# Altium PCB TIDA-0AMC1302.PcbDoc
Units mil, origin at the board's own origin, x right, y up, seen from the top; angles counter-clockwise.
Board outline 1945 x 1500 mil, 2 copper layers (Top Layer, Bottom Layer), stack 62 mil thick; 63 components, 28 nets, 133 pads, 62 vias.
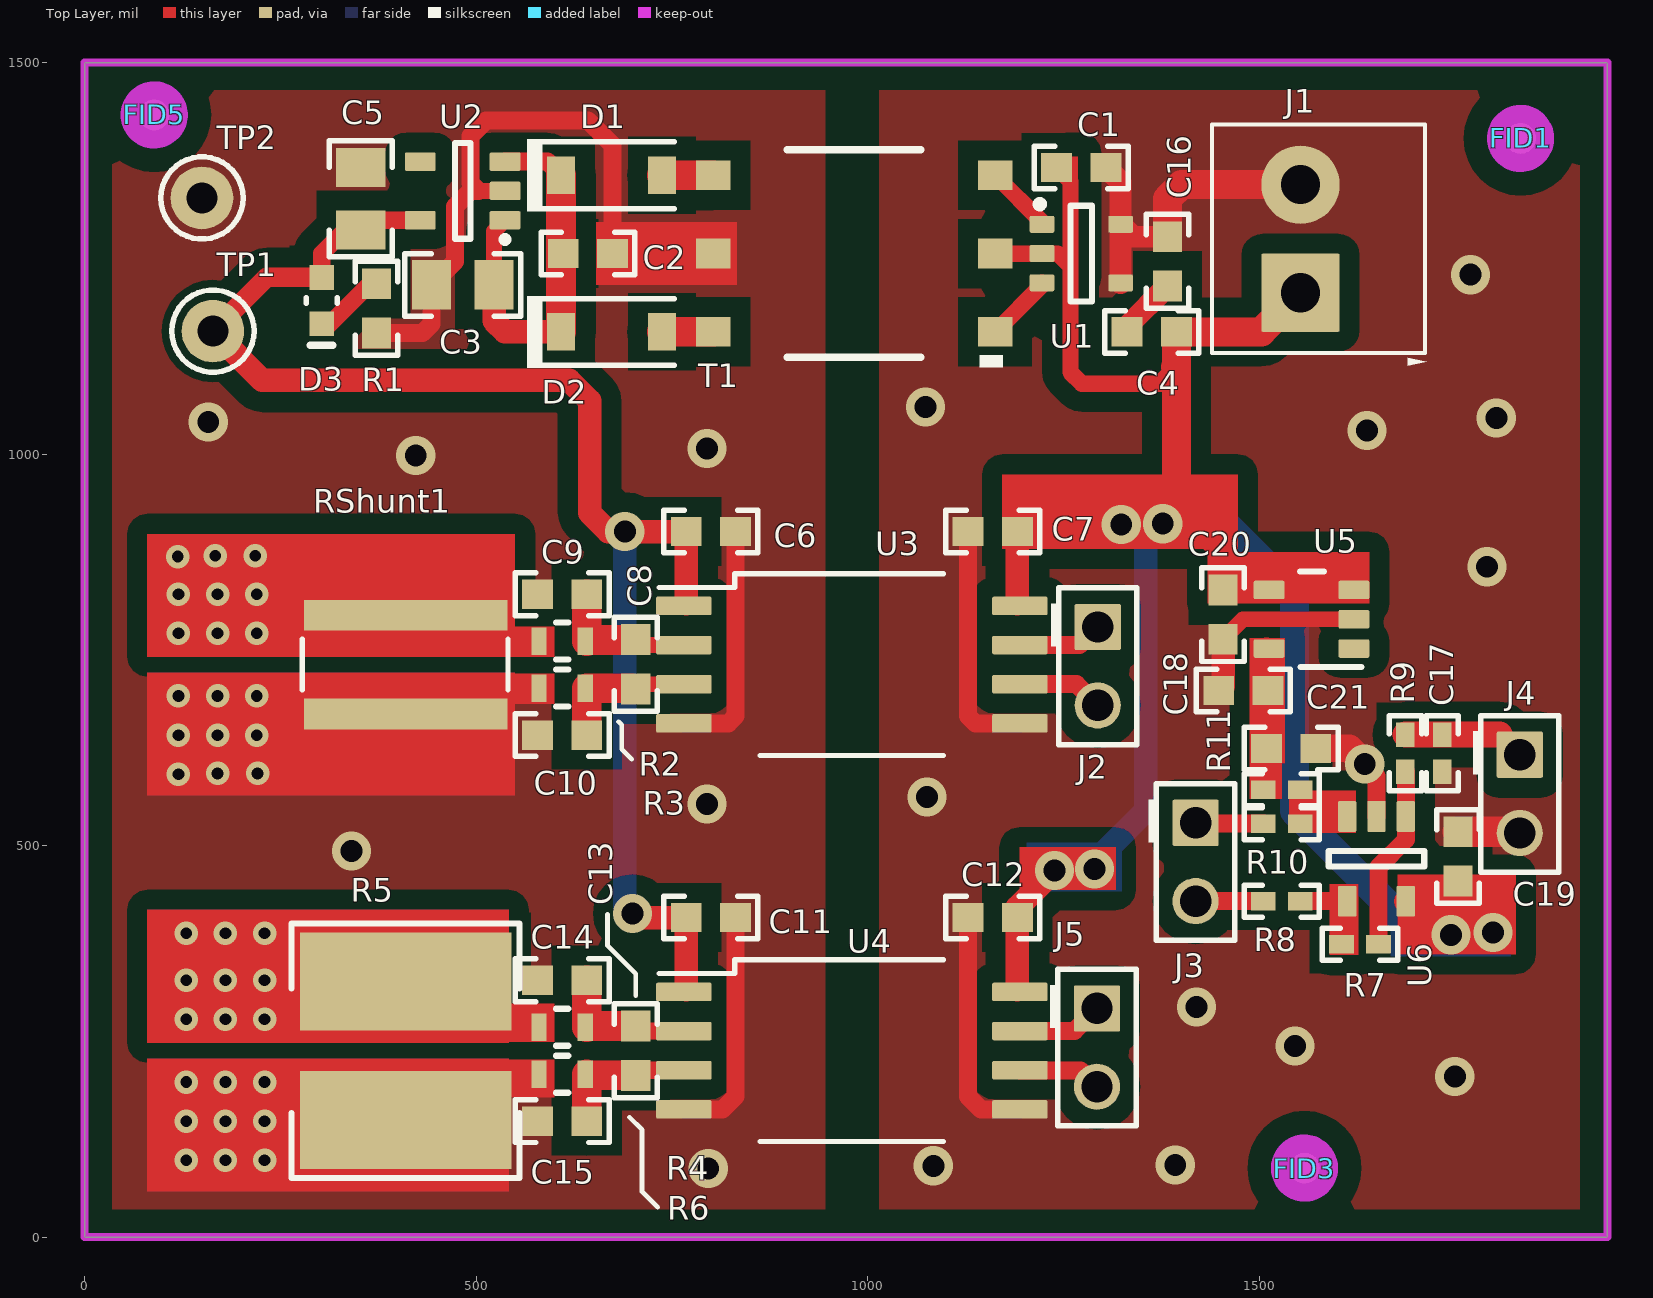
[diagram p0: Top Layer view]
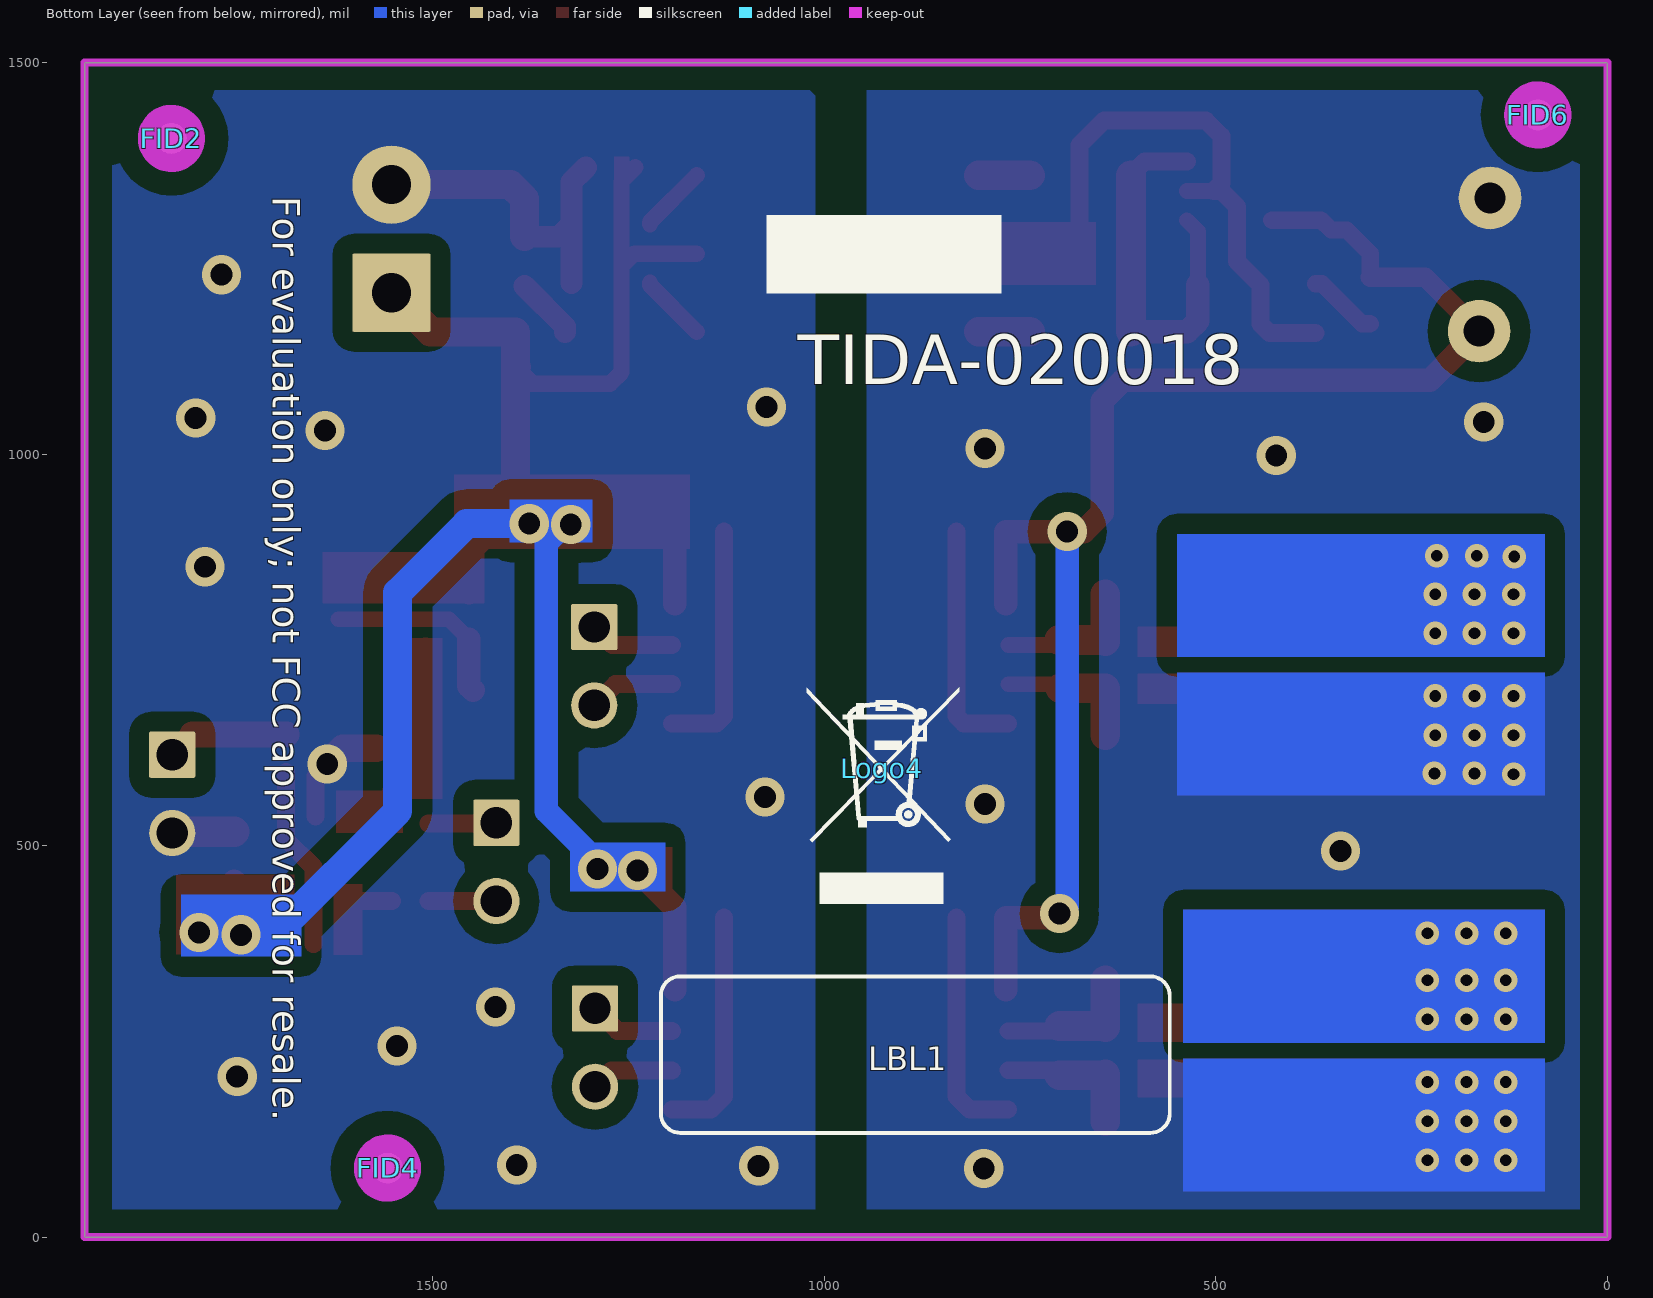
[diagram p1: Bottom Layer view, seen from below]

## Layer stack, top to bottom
Top Solder: solder mask 0.4, Solder Resist, Dk 3.5
Top Layer: signal copper 1.4
Dielectric1: core 59.2, FR-4, Dk 4.8
Bottom Layer: signal copper 1.4
Bottom Solder: solder mask 0.4, Solder Resist, Dk 3.5

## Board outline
0,0 1945,0 1945,1500 0,1500

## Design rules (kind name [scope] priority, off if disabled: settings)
AcuteAngle [All] p1: minimum=4.50000000000000E+0001 checktracksonly=FALSE
AssemblyTestPointUsage [All] p1: valid=2
Clearance samenet [IsPad vs IsVia] p1: gap=6 ignorepadtopadclearanceinfootprint=FALSE except(0: Arc-SMDPad Arc-Hole Track-Hole SMDPad-Hole THPad-Hole Via-Hole Fill-Hole Poly-Hole Region-Hole Text-Hole)
Clearance Clearance_Keepouts [IsKeepOut] p2: gap=30 ignorepadtopadclearanceinfootprint=FALSE except(0: Arc-SMDPad Arc-Hole Track-Hole SMDPad-Hole THPad-Hole Via-Hole Fill-Hole Poly-Hole Region-Hole Text-Hole)
Clearance Clearance_Poly [InPolygon] p3: gap=25 ignorepadtopadclearanceinfootprint=FALSE except(0: Arc-SMDPad Arc-Hole Track-Hole SMDPad-Hole THPad-Hole Via-Hole Fill-Hole Poly-Hole Region-Hole Text-Hole)
Clearance Clearance_FiducialMark [IsKeepOut and InComponentClass('FiducialMark') vs IsPad and InComponentClass('FiducialMark')] p4: gap=0 ignorepadtopadclearanceinfootprint=FALSE
Clearance [All] p5: gap=7.87 ignorepadtopadclearanceinfootprint=FALSE except(0: Arc-SMDPad Arc-Hole Track-Hole SMDPad-Hole THPad-Hole Via-Hole Fill-Hole Poly-Hole Region-Hole Text-Hole)
ComponentClearance ComponentClearance_MountingHoles_FiducialMarks [InComponentClass('Mounting Holes') vs InComponentClass('FiducialMark')] p1: gap=50 collisioncheckmode=3 verticalgap=10 showdistances=FALSE
ComponentClearance ComponentClearance_Shunt [InComponentClass('Header') vs InComponentClass('Shunt')] p2: gap=0 collisioncheckmode=3 verticalgap=0 showdistances=FALSE
ComponentClearance ComponentClearance_Logo [InComponentClass('Logo')] p3: gap=10 collisioncheckmode=3 verticalgap=10 showdistances=FALSE
ComponentClearance ComponentClearance_ScrewToNut [(HasFootprint('NY PMS 440 0025 PH')) vs (HasFootprint('Keystone_1902C'))] p4: gap=5 collisioncheckmode=3 verticalgap=10 showdistances=FALSE
ComponentClearance ComponentClearance_MountingHoles [InComponentClass('Mounting Holes')] p5: gap=250 collisioncheckmode=3 verticalgap=100000 showdistances=FALSE
ComponentClearance ComponentClearance_SmallPassives [HasFootprint('0201*') or HasFootprint('0402*') or HasFootprint('0508') or HasFootprint('0603*') or HasFootprint('0612') or HasFootprint('0805*') or HasFootprint('0815*') or HasFootprint('0830*') or HasFootprint('1206*') or HasFootprint('1210*') or HasFootprint('1808*') or HasFootprint('1812*') or HasFootprint('1825*') or HasFootprint('2010*') or HasFootprint('2220*') or HasFootprint('2225*') or HasFootprint('2512*') or HasFootprint('2728*') or HasFootprint('3518*') vs HasFootprint('0201*') or HasFootprint('0402*') or HasFootprint('0508') or HasFootprint('0603*') or HasFootprint('0612') or HasFootprint('0805*') or HasFootprint('0815*') or HasFootprint('0830*') or HasFootprint('1206*') or HasFootprint('1210*') or HasFootprint('1808*') or HasFootprint('1812*') or HasFootprint('1825*') or HasFootprint('2010*') or HasFootprint('2220*') or HasFootprint('2225*') or HasFootprint('2512*') or HasFootprint('2728*') or HasFootprint('3518*')] p6: gap=14.96 collisioncheckmode=3 verticalgap=10 showdistances=FALSE
ComponentClearance ComponentClearance_THtoSMT [IsThruComponent vs IsSMTComponent] p7: gap=10 collisioncheckmode=3 verticalgap=10 showdistances=FALSE
ComponentClearance ComponentClearance_THtoTH [IsThruComponent vs IsThruComponent] p8: gap=30 collisioncheckmode=3 verticalgap=30 showdistances=FALSE
ComponentClearance [All] p9: gap=10 collisioncheckmode=3 verticalgap=10 showdistances=FALSE
DiffPairsRouting [All] p1: maxlimit=100 minlimit=10 mostfreqgap=10 toplayer_minwidth=15 toplayer_maxwidth=15 toplayer_prefwidth=15 bottomlayer_minwidth=15 bottomlayer_maxwidth=15 bottomlayer_prefwidth=15 maxuncoupledlength=1000
FabricationTestPointUsage TestPointUsage [All] p1: valid=2 allowmultiple=FALSE
FabricationTestpoint Testpoint [All] p1: side=3 testpointundercomponent=TRUE minsize=40 maxsize=100 preferedsize=60 minholesize=0 maxholesize=40 preferedholesize=32 testpointgrid=1 allowsidetop=TRUE allowsidebottom=TRUE usegrid=TRUE gridtolerance=0.01
FanoutControl Fanout_LCC [IsLCC] p1: bgadir=Out bgaviamode=Centered fanoutstyle=Auto fanoutdirection=Alternating viagrid=1 // Fanout_LCC (Default Rule)
FanoutControl Fanout_BGA [IsBGA] p2: bgadir=Out bgaviamode=Centered fanoutstyle=Auto fanoutdirection=Alternating viagrid=1 // Fanout_BGA (Default Rule)
FanoutControl Fanout_Default [All] p4: bgadir=Out bgaviamode=Centered fanoutstyle=Auto fanoutdirection=Alternating viagrid=1 // Fanout_Default (Default Rule)
FanoutControl Fanout_Small [(CompPinCount < 5)] p5: bgadir=Out bgaviamode=Centered fanoutstyle=Auto fanoutdirection=OutThenIn viagrid=1 // Fanout_Small (Default Rule)
HoleSize [All] p1: absolutevalues=TRUE maxlimit=251 minlimit=7.87 maxpercent=80.000 minpercent=20.000
MinimumAnnularRing MinimumAnnularRing_ThermalPadVias [IsVia and InAnyComponent] p1: minimumring=5.91
MinimumAnnularRing [All] p2: minimumring=6
MinimumSolderMaskSliver MinimumSolderMaskSliver_Logo [InComponentClass('Logo') vs InComponentClass('Logo')] p1: minsoldermaskwidth=0.7
MinimumSolderMaskSliver [All] p2: minsoldermaskwidth=3.94
PlaneConnect [All] p1: planeconnectstyle=Relief reliefexpansion=10 reliefentries=4 reliefconductorwidth=10 reliefairgap=10
PolygonConnect [All] p1: connectstyle=Direct reliefconductorwidth=10 reliefentries=4 polygonreliefangle="90 Angle" airgapwidth=10
RoutingVias ThermalPadVias [IsVia and InAnyComponent] p1: holewidth=7.87 width=19.68 viastyle="Through Hole" minholewidth=7.87 minwidth=19.68 maxholewidth=12.99 maxwidth=23.62
RoutingVias [All] p2: holewidth=16 width=34 viastyle="Through Hole" minholewidth=7.87 minwidth=26 maxholewidth=40 maxwidth=65
SilkToBoardRegionClearance [Not ((IsComment or IsDesignator) And (Hide <> 'False')) and not InRegion(1000,500,4000,800)] p1:
SilkToSilkClearance SilkToSilkClearance_Pb-FreeLogo [(HasFootprint('Pb-Free_Overlay_Medium') OR HasFootprint('Pb-Free_Overlay_Small')) vs (HasFootprint('Pb-Free_Overlay_Medium') OR HasFootprint('Pb-Free_Overlay_Small'))] p1: silktosilkclearance=0
SilkToSilkClearance [All] p2: silktosilkclearance=4
SilkToSolderMaskClearance SilkToComponentPadClearance [(IsPad or IsFill or IsRegion) and InAnycomponent] p1: minsilkscreentomaskgap=5 clearancetoexposedcopper=TRUE
SilkToSolderMaskClearance "Silk to Solder Mask Opening" [All] p2: minsilkscreentomaskgap=4 clearancetoexposedcopper=FALSE
SolderMaskExpansion [All] p1: expansion=1.97
Width [All] p1: maxlimit=100 minlimit=6 preferedwidth=10 checkconnectedcopper=TRUE
15 further rules are at their usual default settings.

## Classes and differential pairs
component class Header: J2 J3 J4 J5
component class EVM_Hardware: FID1 FID2 FID3 FID4 FID5 FID6 LBL1 Logo3 Logo4 ZZ1 ZZ2 ZZ3 ZZ4
component class FiducialMark: FID1 FID2 FID3 FID4 FID5 FID6
component class AssemblyNote: ZZ1 ZZ2 ZZ3 ZZ4
component class Label: LBL1
component class BlankSheet: C1 C2 C3 C4 C5 C6 C7 C8 C9 C10 C11 C12 C13 C14 C15 C16 C17 C18 C19 C20 C21 D1 D2 D3 J1 J2 J3 J4 J5 R1 R2 R3 R4 R5 R6 R7 R8 R9 R10 R11 RShunt1 T1 TP1 TP2 U1 U2 U3 U4 U5 U6

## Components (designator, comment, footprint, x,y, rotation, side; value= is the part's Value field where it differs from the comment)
C1 "UMK107AB7105KA-T" 0603 1273,1366 r180 top value=1uF
C2 "C1608X7R1E104K080AA" 0603 643,1256 r0 top value=0.1uF
C3 "JMK212BJ226MG-T" 0805_HV 483,1216 r180 top value=22uF
C4 "C1608X7R1E104K080AA" 0603 1363,1156 r180 top value=0.1uF
C5 "JMK212BJ226MG-T" 0805_HV 352.84,1326 r90 top value=22uF
C6 "C1608X7R1E104K080AA" 0603 800,901 r180 top value=0.1uF
C7 "C1608X7R1E104K080AA" 0603 1160,901 r180 top value=0.1uF
C8 "C1608X7R1E104K080AA" 0603 704,731.5 r270 top value=0.1uF
C9 "CL10B103KB8NCNC" 0603 610,821 r180 top value=0.01uF
C10 "CL10B103KB8NCNC" 0603 610,641 r180 top value=0.01uF
C11 "C1608X7R1E104K080AA" 0603 800,408 r180 top value=0.1uF
C12 "C1608X7R1E104K080AA" 0603 1160,408 r180 top value=0.1uF
C13 "C1608X7R1E104K080AA" 0603 704,238 r270 top value=0.1uF
C14 "CL10B103KB8NCNC" 0603 610,328 r180 top value=0.01uF
C15 "CL10B103KB8NCNC" 0603 610,148 r180 top value=0.01uF
C16 "C1608X7R1E104K080AA" 0603 1383,1246 r90 top value=0.1uF
C17 "C1005X7R1C224K050BC" 0402 1734,618 r270 top value=0.22uF
C18 "C1608X7R1E104K080AA" 0603 1480,698 r180 top value=0.1uF
C19 "C1608X7R1E104K080AA" 0603 1754,486 r270 top value=0.1uF
C20 "C1608X7R1E104K080AA" 0603 1454,795 r90 top value=0.1uF
C21 "C1608X7R1E104K080AA" 0603 1541,624 r0 top value=0.1uF
D1 "MBR0520LT1G" SOD-123 673,1356 r0 top value=20V
D2 "MBR0520LT1G" SOD-123 673,1156 r0 top value=20V
D3 "LG L29K-G2J1-24-Z" "LG L29K_GREEN" 303,1196 r270 top value=Green
FID1 "Fiducial" Fiducial10-20 1834,1403 r0 top
FID2 "Fiducial" Fiducial10-20 1834,1403 r180 bottom
FID3 "Fiducial" Fiducial10-20 1558,88 r0 top
FID4 "Fiducial" Fiducial10-20 1558,88 r180 bottom
FID5 "Fiducial" Fiducial10-20 89,1433 r0 top
FID6 "Fiducial" Fiducial10-20 89,1433 r180 bottom
J1 "ED555/2DS" TERM_BLK_ED555-2DS 1553,1206 r90 top
J2 "PEC02SAAN" CONN_PEC02SAAN 1294,729 r270 top
J3 "PEC02SAAN" CONN_PEC02SAAN 1419,479 r270 top
J4 "PEC02SAAN" CONN_PEC02SAAN 1833,566 r270 top
J5 "PEC02SAAN" CONN_PEC02SAAN 1293,242 r270 top
LBL1 "THT-14-423-10" Label_650x200 884,233 r180 bottom
Logo3 "FCC disclaimer" FCC_disclaimer 2657,717 r180 bottom
Logo4 "WEEE logo" WEEE_Minimum 927,598 r180 bottom
R1 "CRCW06034K70JNEA" 0603 373,1186 r90 top value=4.7k
R2 "TNPW060349R9BEEA" TNPW0603 610,761 r0 top value=49.9
R3 "TNPW060349R9BEEA" TNPW0603 610,701 r0 top value=49.9
R4 "TNPW060349R9BEEA" TNPW0603 610,268 r0 top value=49.9
R5 "CSS2725FTL500" CSS2725_0005 410,238 r90 top value=0.0005
R6 "TNPW060349R9BEEA" TNPW0603 610,208 r0 top value=49.9
R7 "ERA-2AEB1212X" 0402 1629,374 r0 top value=12.1k
R8 "RT0402BRD0710KL" 0402 1529,429 r0 top value=10.0k
R9 "FC0402E50R0BST1" 0402 1687,618 r90 top value=50
R10 "RT0402BRD0710KL" 0402 1529,528 r0 top value=10.0k
R11 "ERA-2AEB1212X" 0402 1529,571 r0 top value=12.1k
RShunt1 "PML100HZPJV1L5" 2512_WIDE 410,731 r90 top value=0.0015
T1 "760390014" Wurth_760390013 983,1256 r180 top value=475uH
TP1 "5001" Keystone5001 164,1157 r90 top
TP2 "5001" Keystone5001 150,1327 r90 top
U1 "SN6501QDBVRQ1" DBV0005A_L 1273,1256 r0 top
U2 "TPS76350QDBVRQ1" DBV0005A_N 483,1336 r180 top
U3 "AMC1302QDWVRQ1" DWV0008A 980,731 r0 top
U4 "AMC1302QDWVRQ1" DWV0008A 980,238 r0 top
U5 "LM4132AQ1MFT2.5" DBV0005A_N 1567,789 r180 top
U6 "OPA376AQDBVRQ1" DBV0005A_N 1650,483 r270 top
ZZ1 "This Assembly Note is for PCB labels only" AssemblyNoteLabel 185,3938 r0 top
ZZ2 "These assemblies are ESD sensitive, ESD precautions shall be observed." AssemblyNote 185,3829.11 r0 top
ZZ3 "These assemblies must be clean and free from flux and all contaminants. Use of no clean flux is not acceptable." AssemblyNote 185,3740.56 r0 top
ZZ4 "These assemblies must comply with workmanship standards IPC-A-610 Class 2, unless otherwise specified." AssemblyNote 185,3652 r0 top

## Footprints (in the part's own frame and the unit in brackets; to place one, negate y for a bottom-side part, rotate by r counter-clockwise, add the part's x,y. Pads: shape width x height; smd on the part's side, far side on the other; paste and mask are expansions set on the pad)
0402 [mm] "0402 from SM-752 data"
  rect 0.8x0.6 smd: 1(-0.6,0) 2(0.6,0)
  silkscreen extent -1.22,-0.52 1.22,0.52, body extent -0.55,-0.3 0.55,0.3, height 0.6
0603 [mm] "0603 from SM-752 data"
  rect 1x0.95 smd: 1(-0.8,0) 2(0.8,0)
  silkscreen extent -1.52,-0.69 1.52,0.69, body extent -0.87,-0.47 0.87,0.47, height 1
0805_HV [mil] "0805 with 30mil clearance between pads"
  rect 50x63 smd: 1(-40,0) 2(40,0)
  silkscreen extent -74,-40 74,40, body extent -43,-29 43,29, height 57
2512_WIDE [mm] "Ohmite recommended land pattern"
  rect 1x6.6 smd: 1(-1.6,0) 2(1.6,0)
  silkscreen extent -0.82,-3.32 0.82,3.35, body extent -1.65,-3.25 1.65,3.25, height 0.7
AssemblyNote [mil] "Assembly Note"
AssemblyNoteLabel [mil] "Assembly Note for PCB Labels"
CONN_PEC02SAAN [mm] "SULLINS"
  rrect7% 1.5x1.5 hole 1.016: 1(-1.27,0)
  round 1.5 hole 1.016: 2(1.27,0)
  silkscreen extent -2.54,-1.52 2.54,1.27, body extent -2.54,-1.27 2.54,1.27, height 8.38
CSS2725_0005 [mm] "STACKPOLE ELECTRONICS"
  rect 3.18x6.86 smd: 1(-2.25,0) 2(2.25,0)
  silkscreen extent -4.13,-3.7 4.13,3.7, body extent -3.53,-3.35 3.53,3.35, height 1.24
DBV0005A_L [mm] "SOT23, 5-Leads, Body 2.9x1.6mm, Pitch 0.95mm, Lead Span 2.8mm, IPC High Density"
  rrect18% 0.8x0.55 smd: 1(-1.275,0.95) 2(-1.275,0) 3(-1.275,-0.95) 4(1.275,-0.95) 5(1.275,0.95)
  silkscreen extent -0.35,-1.55 0.35,1.55, body extent -1.42,-1.46 1.42,1.46, height 1.09
DBV0005A_N [mm] "SOT23, 5-Leads, Body 2.9x1.6mm, Pitch 0.95mm, Lead Span 2.8mm, IPC Medium Density"
  rrect17% 1x0.6 smd: 1(-1.375,0.95) 2(-1.375,0) 3(-1.375,-0.95) 4(1.375,-0.95) 5(1.375,0.95)
  silkscreen extent -0.25,-1.55 0.25,1.55, body extent -1.42,-1.46 1.42,1.46, height 1.09
DWV0008A [mm] "SOIC, 8-Leads, Body 5.95x7.6mm (max), Pitch 1.27mm"
  rrect17% 1.8x0.6 smd: 1(-5.45,1.905) 2(-5.45,0.635) 3(-5.45,-0.635) 4(-5.45,-1.905) 5(5.45,-1.905) 6(5.45,-0.635) 7(5.45,0.635) 8(5.45,1.905)
  silkscreen extent -6.25,-2.95 2.98,2.95, body extent -5.77,-2.92 5.77,2.93, height 2.67
FCC_disclaimer [mil]
Fiducial10-20 [mm]
  round 1 smd mask+0.5: 1(0,0)
  Top Layer keep-out circle w1.178: c0,0 r0.5
Keystone5001 [mil] "For Keystone 500x miniature loop terminals"
  round 80 hole 40: 1(0,0)
  silkscreen extent -52,-52 52,52, body extent -49,-49 49,49, height 182
Label_650x200 [mil] "Thermal Transfer Label"
  round 1 on Mech14: 0(0,0)
  silkscreen extent -325,-100 325,100, body extent -325,-100 325,100, height 1
"LG L29K_GREEN" [mm] "OSRAM"
  rect 0.8x0.8 smd paste-0.4: 1(-0.75,0) 2(0.75,0)
  silkscreen extent -0.1,-0.5 1.45,0.5, body extent -0.9,-0.45 0.9,0.45, height 0.67
SOD-123 [mm] "On Semi recommended land pattern"
  rect 0.915x1.22 smd: 1(-1.637,0) 2(1.637,0)
  silkscreen extent -2.74,-1.17 2.03,1.17, body extent -1.93,-0.9 1.93,0.9, height 1.35
TERM_BLK_ED555-2DS [mil]
  rrect4% 100x100 hole 50: 1(0,0)
  round 100 hole 50: 2(138,0)
  silkscreen extent -93,-161 215,113, body extent -69,-150 207,106, height 323
TNPW0603 [mm] "Vishay"
  rect 0.5x0.9 smd: 1(-0.75,0) 2(0.75,0)
  silkscreen extent -0.2,-0.6 0.2,0.6, body extent -0.85,-0.47 0.85,0.47, height 0.55
WEEE_Minimum [mil] "WEEElie bin"
  silkscreen extent -95,-172 99,104
Wurth_760390013 [mil] "Wurth"
  rect 44x38 smd: 1(-180,100) 2(-180,0) 3(-180,-100) 4(180,-100) 5(180,0) 6(180,100)
  silkscreen extent -190,-132 85,145, body extent -198,-135 198,130, height 166

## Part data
C1: library part CMP-0007508-5, "CAP, CERM, 1 uF, 50 V, +/- 10%, X7R, 0603", Cap_Case=0603, Manufacturer="Taiyo Yuden", Supplier Part Number 1=587-3247-1-ND, TempCo=X7R, Tolerance_%=10%, Value1=Unknown, Value2=50V, ValueDisplayed=1uF
C2 C4 C6 C7 C8 C11 C12 C13 C16 C18 C19 C20 C21: library part CMP-0007039-5, "CAP, CERM, 0.1 uF, 25 V, +/- 10%, X7R, 0603", Cap_Case=0603, Manufacturer=TDK, Supplier Part Number 1=445-1316-1-ND, TempCo=X7R, Tolerance_%=10%, Value1=Unknown, Value2=25V, ValueDisplayed=0.1uF
C3 C5: library part CMP-0008391-2, "CAP, CERM, 22 uF, 6.3 V, +/- 20%, X5R, 0805", Cap_Case=0805, Manufacturer="Taiyo Yuden", Supplier Part Number 1=587-1305-1-ND, TempCo=X5R, Tolerance_%=20%, Value1=Unknown, Value2=6.3V, ValueDisplayed=22uF
C9 C10 C14 C15: library part CMP-0007109-5, "CAP, CERM, 0.01 uF, 50 V, +/- 10%, X7R, 0603", Cap_Case=0603, Manufacturer="Samsung Electro-Mechanics", Supplier Part Number 1=1276-1921-1-ND, TempCo=X7R, Tolerance_%=10%, Value1=Unknown, Value2=50V, ValueDisplayed=0.01uF
C17: library part CMP-0006293-2, "CAP, CERM, 0.22 uF, 16 V, +/- 10%, X7R, 0402", Cap_Case=0402, Manufacturer=TDK, Supplier Part Number 1=445-5936-1-ND, TempCo=X7R, Tolerance_%=10%, Value1=Unknown, Value2=16V, ValueDisplayed=0.22uF
D1 D2: library part CMP-0028524-1, "Diode, Schottky, 20 V, 0.5 A, SOD-123", Manufacturer="ON Semiconductor", Supplier Part Number 1=MBR0520LT1GOSCT-ND, Value1=0.5A, Value2=0.385V
D3: library part CMP-0002874-1, "LED, Green, SMD", Color=green, Manufacturer=OSRAM, Supplier Part Number 1=475-2709-1-ND, Value1=W, Value2=1.7V
FID1 FID2 FID3 FID4 FID5 FID6: library part CMP-0077181-1, "Fiducial mark.  There is nothing to buy or mount.", Manufacturer=N/A
J1: library part CMP-0074913-1, "Terminal Block, 3.5mm Pitch, 2x1, TH", Color=Grey, Current_A=6A, Manufacturer="On-Shore Technology", Supplier Part Number 1=ED1514-ND, Voltage_V=150V
J2 J3 J4 J5: library part CMP-0002337-1, "Header, 100mil, 2x1, Tin, TH", Color=Black, Current_A=3A, Manufacturer="Sullins Connector Solutions", Supplier Part Number 1=S1012E-02-ND, Voltage_V=1.8kV
LBL1: library part CMP-0003625-1, "Thermal Transfer Printable Labels, 0.650\" W x 0.200\" H - 10,000 per roll", Manufacturer=Brady, Supplier Part Number 1=97C5133
Logo3: library part CMP-0074847-1, "FCC_disclaimer"
Logo4: library part CMP-0074769-1
R1: library part CMP-0025817-4, "RES, 4.7 k, 5%, 0.1 W, AEC-Q200 Grade 0, 0603", Manufacturer=Vishay-Dale, Power_W=100mW, Supplier Part Number 1=541-4.7KGCT-ND, TempCo="200 ppm/C", Tolerance_%=5%, Value2=0.1W, Value_Code=4k70, ValueDisplayed=4.7k
R2 R3 R4 R6: library part CMP-0025693-1, "RES, 49.9, 0.1%, 0.1 W, AEC-Q200 Grade 1, 0603", Manufacturer=Vishay-Dale, Power_W=100mW, Supplier Part Number 1=541-2031-1-ND, TempCo="25 ppm/C", Tolerance_%=0.1%, Value2=0.1W, Value_Code=49R9, ValueDisplayed=49.9
R5: library part CMP-0015026-2, "RES, 0.0005, 1%, 4 W, RES_2725", Manufacturer="Stackpole Electronics Inc", Power_W=4W, Supplier Part Number 1=CSS2725FTL500CT-ND, TempCo="50 ppm/C", Tolerance_%=1%, Value_Code=L5000, ValueDisplayed=0.0005
R7 R11: library part CMP-0083631-1, "RES, 12.1 k, 0.1%, 0.063 W, AEC-Q200 Grade 0, 0402", Manufacturer=Panasonic, Power_W=63mW, Supplier Part Number 1=P12.1KDCCT-ND, TempCo="25 ppm/C", Tolerance_%=0.1%, Value2=0.063W, Value_Code=12k1, ValueDisplayed=12.1k
R8 R10: library part CMP-0065360-1, "RES, 10.0 k, .1%, .0625 W, 0402", Manufacturer="Yageo America", Power_W=62.5mW, Supplier Part Number 1=YAG1346CT-ND, TempCo="25 ppm/C", Tolerance_%=0.1%, Value1=.1%, Value2=.0625W, Value_Code=10k0, ValueDisplayed=10.0k
R9: library part CMP-0026791-1, "RES, 50, 0.1%, 0.05 W, 0402", Manufacturer=Vishay-Dale, Power_W=50mW, Supplier Part Number 1=FC0402-50BWCT-ND, TempCo="25 ppm/C", Tolerance_%=0.1%, Value2=0.05W, Value_Code=50R0, ValueDisplayed=50
RShunt1: library part CMP-0084409-1, "RES, 0.0015, 5%, 2 W, 2512 WIDE", Manufacturer=Rohm, Power_W=2W, TempCo="100 ppm/C", Tolerance_%=5%, Value_Code=1L500, ValueDisplayed=0.0015
T1: library part CMP-0030718-1, "Transformer, 475uH, SMT", Manufacturer="Wurth Elektronik", Supplier Part Number 1=732-4458-1-ND, ValueDisplayed=475uH
TP1 TP2: library part CMP-0055138-1, "Test Point, Miniature, Black, TH", Color=Black, Manufacturer=Keystone, Supplier Part Number 1=36-5001-ND
U1: library part CMP-0076093-1, "Automotive Low-Noise 350 mA, 410 kHz Transformer Driver, DBV0005A (SOT-23-5)", Alternate Manufacturer="Texas Instruments"
U2: library part CMP-0035574-1, "Single Output Automotive LDO, 150 mA, Fixed 5 V Output, 2.7 to 10 V Input, 5-pin SOT-23 (DBV), -40 to 125 degC, Green (RoHS & no Sb/Br)", Manufacturer="Texas Instruments"
U3 U4: library part CMP-0080587-1, "Precision Reinforced Isolated Amplifier for Current Sensing, DWV0008A (SOIC-8)", Alternate Manufacturer="Texas Instruments"
U5: library part CMP-0081400-1, "Automotive SOT23 Precision Low Dropout Voltage Reference, DBV0005A (SOT-23-5)", Alternate Manufacturer="Texas Instruments", Alternate PartNumber=LM4132AQ1MFR2.5, Operating Temprature Range="-40 to 125 C", Rating=Automotive
U6: library part CMP-0041022-2, "Automotive Catalog Precision, Low Noise, Low Iq Operational Amplifier, 2.2 to 5.5 V, -40 to 125 degC, 5-pin SOT23 (DBV5), Green (RoHS & no Sb/Br)", Manufacturer="Texas Instruments", Total Supply Voltage(Max)(+5V is 5, +/-5V is 10)=5.5, Total Supply Voltage(Min)(+5V is 5, +/-5V is 10)=2.2
ZZ1: library part CMP-0003616-3
ZZ2: library part CMP-0077236-1
ZZ3: library part CMP-0077237-1
ZZ4: library part CMP-0077238-1

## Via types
v1: diameter 30, hole 15, Top Layer to Bottom Layer, 36 vias
v2: diameter 50, hole 28, Top Layer to Bottom Layer, 26 vias

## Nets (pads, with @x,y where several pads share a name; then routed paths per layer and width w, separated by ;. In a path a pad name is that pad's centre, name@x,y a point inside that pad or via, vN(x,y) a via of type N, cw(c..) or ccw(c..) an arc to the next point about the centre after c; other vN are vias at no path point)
5V_ISO: C5.1 C6.2 C11.2 D3.1 TP1.1 U2.5 U3.1 U4.1 | length 1882.9
  Top Layer w22: D3.1 303,1256.16 332.84,1286 C5.1 365.44,1298.6 U2.5
  Top Layer w25: TP1.1 232.53,1225.53 D3.1
  Top Layer w30: TP1.1 227,1094 619,1094 645,1068 645,925 669,901 v2(690,901) C6.2 U3.1@768.5,809.07 ; v2(700,413) 705,408 C11.2 U4.1@768.5,316.07
  Bottom Layer w30: v2(690,901) 690,422.04 699.04,413 v2(700,413)
GND: C1.1 C7.2 C12.2 C16.2 C17.2 C18.2 C19.1 C20.1 C21.2 J1.2 J4.2 U1.4 U1.5 U3.5 U4.5 U5.2 U6.2 | length 1502.3
  Top Layer w20: C20.1 1479.43,788.94 1621.13,788.94 U5.2
  Top Layer w23: C12.2 1128.5,179.5 1145,163 U4.5 ; C7.2 1128.5,665.37 1137.87,656 U3.5 ; U6.2 v2@1650,589
  Top Layer w28: C1.1 1323.2,1347.3 U1.5 ; U1.4 U1.5 ; C16.2 1339.1,1277.5 U1.5
  Top Layer w30: C18.2 1454,703.5 C20.1
  Top Layer w35: C21.2 1615,624 v2(1635,604)
  Top Layer w37: C16.2 1383,1326 1401,1344 J1.2
  Top Layer w39: C19.1 1831.5,517.5 J4.2
  other v2: 1084,91 1393,92 1750,205 1546,244 1420,294 1076,562 1791,856 1638,1030 1803,1046 1074,1060 1770,1229
ISOGND: C2.2 C3.2 C5.2 C6.1 C9.2 C10.2 C11.1 C14.2 C15.2 R1.1 R3.1 R5.1 R6.1 RShunt1.1 T1.5 TP2.1 U2.2 U3.4 U4.4 | length 1390.7
  Top Layer w20: 503,1336 U2.2
  Top Layer w23: R1.1 431.5,1154.5 443,1166 C3.2 473,1246 473,1316 493,1336 503,1336 492.84,1346.16 492.84,1405.84 513,1426 643,1426 674.5,1394.5 C2.2 ; U4.4 815,163 831.5,179.5 C11.1 ; U3.4 822.13,656 831.5,665.37 C6.1
  Top Layer w38: 744.5,1256 T1.5
  other v1: 130,98 180,98 230,98 130,148 180,148 230,148 130,198 180,198 230,198 120,591 170,592 221,592 120,641 170,641 220,641 120,691 170,691 220,691
  other v2: 796.61,87.39 341,493 795,553 423,998 795,1007 158,1041
NetC2_1: C2.1 C3.1 D1.1 D2.1 U2.1 U2.3 | length 504.4
  Top Layer w20: C3.1 523,1284.46 U2.1
  Top Layer w23: U2.3 591.13,1373.4 D1.1
  Top Layer w30: C3.1 523,1170 537,1156 D2.1
  Top Layer w38: D2.1 D1.1
NetC4_2: C4.2 C16.1 | length 79.8
  Top Layer w28: C4.2 1331.5,1163.01 C16.1
NetC8_1: C8.1 C9.1 R2.2 U3.2 | length 175.9
  Top Layer w20: C8.1@706.5,756 U3.2
  Top Layer w38: R2.2@641.5,761 C9.1 ; R2.2@642.99,762.5 C8.1@700,762.5
NetC8_2: C8.2 C10.1 R3.2 U3.3 | length 175.9
  Top Layer w20: C8.2@706.5,706 U3.3
  Top Layer w38: C10.1 641.5,701 C8.2@698.5,701
NetC13_1: C13.1 C14.1 R4.2 U4.2 | length 185.1
  Top Layer w22: C13.1@706.5,263 U4.2
  Top Layer w23: C13.1@700,269.5 C13.1@706.5,263
  Top Layer w38: R4.2@641.5,268 C14.1 ; R4.2@642.99,269.5 C13.1@700,269.5
NetC13_2: C13.2 C15.1 R6.2 U4.3 | length 175.9
  Top Layer w22: C13.2@706.5,213 U4.3
  Top Layer w38: C15.1 R6.2@641.5,208 ; R6.2@642.99,206.5 C13.2@700,206.5
NetD1_2: D1.2 T1.4 | length 65.5
  Top Layer w38: D1.2 T1.4
NetD2_2: D2.2 T1.6 | length 65.5
  Top Layer w38: D2.2 T1.6
NetD3_2: D3.2 R1.2 | length 91.1
  Top Layer w22: D3.2 313.47,1166.47 364.5,1217.5 R1.2
NetJ2_1: J2.1 U3.7 | length 109
  Top Layer w23: U3.7 1271,756 J2.1
NetJ2_2: J2.2 U3.6 | length 110.6
  Top Layer w23: U3.6 1267,706 J2.2
NetJ3_1: J3.1 R10.1 | length 85.4
  Top Layer w23: J3.1@1420,528 R10.1
NetJ3_2: J3.2 R8.1 | length 86.4
  Top Layer w23: J3.2 R8.1
NetJ5_1: J5.1 U4.7 | length 110.4
  Top Layer w23: U4.7 1264,263 J5.1
NetJ5_2: J5.2 U4.6 | length 107.1
  Top Layer w23: U4.6 1272,213 J5.2
NetR7_1: R7.1 R8.2 U6.4 | length 107.5
  Top Layer w23: R8.2 U6.4@1612.46,429 ; R7.1 U6.4@1605.38,421.65
NetR7_2: R7.2 R9.1 U6.1 | length 234.4
  Top Layer w23: R7.2 1652.62,472.62 1687.4,507.4 U6.1 R9.1@1687.4,593.98
NetR10_2: R10.2 R11.2 U6.3 | length 43
  Top Layer w23: R10.2 R11.2
NetT1_1: T1.1 U1.3 | length 87.4
  Top Layer w21: T1.1 1222.8,1215.8 U1.3
NetT1_3: T1.3 U1.1 | length 87.4
  Top Layer w21: T1.3 1222.8,1296.2 U1.1
OUTPUT: C17.1 J4.1 R9.2 | length 156.6
  Top Layer w30: J4.1@1807.38,641.62 J4.1
  Top Layer w33: R9.2 J4.1@1807.38,641.62
REFOUT2.5: C18.1 C21.1 R11.1 U5.5 | length 124.2
  Top Layer w35: C21.1 U5.5@1509.5,748.24
shunt1_P: R2.1 RShunt1.2
  other v1: 120,771 170,771 220,771 120,821 170,821 220,821 119,869 167,870 218,870
shunt2_P: R4.1 R5.2
  other v1: 130,278 180,278 230,278 130,328 180,328 230,328 130,388 180,388 230,388
VCC_5V: C1.2 C4.1 C7.1 C12.1 C19.2 C20.2 J1.1 T1.2 U1.2 U3.8 U4.8 U5.3 U5.4 U6.5 | length 3025.2
  Top Layer w21: T1.2 U1.2 1243,1256 1259.22,1239.78 ; C7.1 1250,901 1259.22,910.22 ; C1.2 1259.22,1348.28 1259.22,1239.78 ; 1393.42,1110.93 1372.5,1090 1273.44,1090 1259.22,1104.22 1259.22,1239.78
  Top Layer w23: C20.2@1454.09,826.4 U5.4 U5.3
  Top Layer w30: U4.8@1191.5,316.07 C12.1 1191.5,420.88 v2(1238.79,468.17) ; U3.8@1191.5,809.07 C7.1 ; U6.5 1728.36,428.87 C19.2
  Top Layer w37: 1250,901 1340,901 1394.5,955.5 1394.5,1112 ; v2(1377,911) 1423,911 1454,880 C20.2 ; 1393.42,1110.93 1394.5,1112 ; J1.1 1503,1156 C4.1 1394.5,1112
  Bottom Layer w30: v2(1290,470) 1290,479 1355,544 1355,886.96 1331.96,910 v2(1324,910)
  Bottom Layer w37: v2(1377,911) 1457,911 1545,823 1545,544 1703,386 v2(1745,386)
  other v2: 1799,389
pads on no net: FID1.1 FID2.1 FID3.1 FID4.1 FID5.1 FID6.1 LBL1.0 U2.4 U5.1

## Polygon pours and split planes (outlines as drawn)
ISOGND on Top Layer "TOP_LAYER_NONET_P000" (solid, remove dead copper, pour order 6): 0,1500 946,1500 946,0 0,0
GND on Top Layer "TOP_LAYER_NONET_P002" (solid, remove dead copper, pour order 8): 1015,1500 1015,0 1943,0 1943,1500
GND on Bottom Layer "TOP_LAYER_NONET_P002" (solid, remove dead copper, pour order 7): 1012,1500 1012,0 1943,0 1943,1500
ISOGND on Bottom Layer "BOTTOM_LAYER_NONET_P004" (solid, remove dead copper, pour order 9): 0,1500 946,1500 946,0 0,0

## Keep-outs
Keep-Out Layer:
  the board outline again, w10
  text ".Layer_Name" at 577,-858.49 h60

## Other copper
Top Layer:
  rectangle net VCC_5V: 1172,879 1473,974
  rectangle net VCC_5V: 1194,443 1317,498
  rectangle net VCC_5V: 1372.5,1079 1397,1090
  rectangle net ISOGND: 653,1216 833,1296
  rectangle net shunt1_P: 280,741 537.95,821
  rectangle net ISOGND: 280,641 537.95,721
  rectangle net shunt1_P: 470,741 600,779.7
  rectangle net ISOGND: 470,681 600,719.7
  rectangle net shunt2_P: 270,249.3 600,298
  rectangle net ISOGND: 270,178 600,226.7
  rectangle net shunt2_P: 80,248 541.89,418
  rectangle net ISOGND: 80,58 541.89,228
  rectangle net ISOGND: 80,564 550,721
  rectangle net shunt1_P: 80,741 550,898
  rectangle net NetR7_1: 1590,360 1627,451
  rectangle net REFOUT2.5: 1488,559.19 1529,765
  rectangle net REFOUT2.5: 1488,605 1533,765
  rectangle net NetR10_2: 1538,516 1624,570
  rectangle net VCC_5V: 1434,809 1641,875
  rectangle net VCC_5V: 1677,361 1828,463
  rectangle net VCC_5V: 1249,1221 1269,1379.7
  text ".Layer_Name" at 577,-858.49 h60
Bottom Layer:
  rectangle net VCC_5V: 1668,358 1822,437.66
  rectangle net VCC_5V: 1203.13,441 1325,503.83
  rectangle net VCC_5V: 1296,887 1402,942
  rectangle net shunt1_P: 80,741 550,898
  rectangle net ISOGND: 80,564 550,721
  rectangle net shunt2_P: 80,248 541.89,418
  rectangle net ISOGND: 80,58 541.89,228
  text ".Layer_Name" at 577,-858.49 h60

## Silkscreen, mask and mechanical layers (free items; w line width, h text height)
Top Overlay:
  circle w10: c1220,1319 r4.12
  circle w10: c537,1274 r3.16
  lines w6: 668,412 668,372 704,336 704,308 ; 682,658 686,654 686,623 699,610 ; 696,153 712,137 712,58 732,38
  text ".Layer_Name" at 577,-858.49 h60
Bottom Overlay:
  rectangle: 774,1205 1074,1305
  text "TIDA-020018" at 1034,1068 h108.27
  text ".Layer_Name" at 577,-858.49 h60
Top Paste:
  text ".Layer_Name" at 577,-858.49 h60
Bottom Paste:
  text ".Layer_Name" at 577,-858.49 h60
Top Solder:
  rectangle: 80,58 541.89,228
  rectangle: 80,248 540,418
  rectangle: 80,741 550,898
  rectangle: 80,564 550,721
  text ".Layer_Name" at 577,-858.49 h60
  text ".Layer_Name" at 577,-858.49 h60
Bottom Solder:
  rectangle: 80,741 550,898
  rectangle: 80,564 550,721
  rectangle: 80,248 541.89,418
  rectangle: 80,58 541.89,228
  text ".Layer_Name" at 577,-858.49 h60
Drill Guide:
  text ".Layer_Name" at 577,-858.49 h60
M1 Board Outline:
  the board outline again, w10
  text "'.Layer_Name'" at 601,-849 h50
M2 Board Dimensions:
  rectangle: 0,-275 125,-150
  rectangle: 125,-400 500,-275
  lines w7: 0,-275 1000,-275 ; 125,-400 125,-150 ; 250,-400 250,-150 ; 500,-400 500,-150 ; 750,-400 750,-150 ; 0,-400 1000,-400 1000,-150 0,-150 0,-400
M3 3D STEP Top:
  text ".Layer_Name" at 577,-858.49 h60
M4 3D STEP Bottom:
  text ".Layer_Name" at 577,-858.49 h60
M5 Assembly Top:
  circle w10: c532,1278 r3.61
  circle w10: c1224,1321 r3.61
  circle w10: c1623,725 r3.61
  circle w10: c1710,532 r3.61
  circle w10: c1869,648 r3.61
  circle w10: c1451,556 r3.61
  circle w10: c1329,318 r3.61
  circle w10: c1330,810 r3.61
  circle w10: c1615,1159 r3.61
  lines w10: -292,-930.17 6308,-930.17 ; -292,-726.83 6310,-726.83 ; -292,-523.5 -292,-1133.5 3713,-1133.5 6310,-1133.5 6310,-523.5 -291.5,-523.5 -291.5,-1133.5 1284,-1133.5 ; 2173,-1133.5 2173,-523.5 ; 3440,-726.83 3440,-523.5 ; 4280,-726.83 4280,-523.5 ; 4902,-1140 4902,-937.17
  text "COMPONENTS MARKED 'DNP' SHOULD NOT BE POPULATED." at 1153.5,-318.5 h60
  text "ASSEMBLY VARIANT:" at 1153,-434 h60
  text ".VariantName" at 2189,-434 h60
  text "PCB VIEWED FROM TOP SIDE" at -228.5,-655.67 h60
  text "BOARD #:" at 2248,-655.67 h60
  text "REV:" at 3638,-655.67 h60
  text ".PCB_Rev" at 3929.5,-655.67 h60
  text "SVN REV:" at 4476,-655.67 h60
  text ".VersionControl_RevNumber" at 4982,-655.67 h60
  text "TIDA-020018" at 2736,-659 h60
  text "TID #:" at 2248,-859 h60
  text "020018" at 2793.5,-859 h60
  text ".layer_Name" at 651,-874 h60
  text ".plot_File_Name" at 446,-1054 h60
  text "PLOT NAME =" at -228.5,-1064.34 h60
  text "GENERATED    :" at 2250,-1064.34 h60
  text ".Print_Date" at 3119.5,-1064.34 h60
  text ".Print_Time" at 3848.5,-1064.34 h60
  text "TEXAS INSTRUMENTS" at 5113,-1064.34 h60
M6 Assembly Bottom:
  lines w10: -292.5,-727.33 6309.5,-727.33 ; -290.5,-930.67 6309.5,-930.67 ; 1115.5,-1140.5 1115.5,-937.67 ; 1737.5,-727.33 1737.5,-524 ; 2577.5,-727.33 2577.5,-524 ; 3844.5,-1134 3844.5,-524 ; 4733.5,-1134 6309,-1134 6309,-524 -292.5,-524 -292.5,-1134 2304.5,-1134 6309.5,-1134 6309.5,-524
  text "COMPONENTS MARKED 'DNP' SHOULD NOT BE POPULATED." at 6102,-318 h60
  text ".VariantName" at 5058,-434 h60
  text "ASSEMBLY VARIANT:" at 6097,-434 h60
  text ".VersionControl_RevNumber" at 1035.5,-656.17 h60
  text "SVN REV:" at 1541.5,-656.17 h60
  text ".PCB_Rev" at 2088,-656.17 h60
  text "REV:" at 2379.5,-656.17 h60
  text ".PRJ_Number" at 3224,-656.17 h60
  text "BOARD #:" at 3769.5,-656.17 h60
  text "PCB VIEWED FROM BOTTOM SIDE" at 6246,-656.17 h60
  text ".layer_Name" at 5763,-843 h60
  text ".TID" at 3224,-859.5 h60
  text "TID #:" at 3769.5,-859.5 h60
  text "TEXAS INSTRUMENTS" at 904.5,-1064.84 h60
  text ".Print_Time" at 2169,-1064.84 h60
  text ".Print_Date" at 2898,-1064.84 h60
  text "GENERATED    :" at 3767.5,-1064.84 h60
  text ".plot_File_Name" at 5440.5,-1064.84 h60
  text "PLOT NAME =" at 6246,-1064.84 h60
M9 Title Sheet:
  drawing of 57 lines, arcs and shapes, not listed
  text "1" at 739.84,8036.5 h70
  text "2" at 3235.5,8036.5 h70
  text "3" at 5724.84,8036.5 h70
  text "4" at 8231.51,8036.5 h70
  text "5" at 10730.5,8036.5 h70
  text "6" at 13235.5,8036.5 h70
  text "A" at -416.5,6893.5 h70
  text "A" at 14383.5,6893.5 h70
  text "B" at -416.5,4513.5 h70
  text "B" at 14383.5,4513.5 h70
  text "C" at -416.5,2138.5 h70
  text "C" at 14383.5,2138.5 h70
  text "PROJECT TITLE:" at 11343.5,277.5 h45
  text ".PRJ_Title" at 11393.5,144.17 h70
  text "DESIGNED FOR:" at 11343.5,-23.5 h45
  text ".PRJ_Customer" at 11393.5,-163.5 h70
  text "D" at -416.5,-231.5 h70
  text "D" at 14383.5,-231.5 h70
  text "FILE NAME:" at 11343.5,-323.5 h45
  text ".PCB_File_Name_No_Path" at 11393.5,-443.5 h70
  text "Texas Instruments (TI) and/or its licensors do not warrant the accuracy or completeness of this specification" at 6374,-605.34 h45
  text "ENGINEER:" at 11343.5,-613.5 h45
  text "LAYOUT BY:" at 12848.5,-613.5 h45
  text "or any information contained therein. TI and/or its licensors do not warrant that this design will meet" at 6329.01,-718 h45
  text "SANDEEP" at 11393.5,-768.49 h70
  text ".PCB_Layout" at 12899,-768.49 h70
  text "the specifications, will be suitable for your application or fit for any particular purpose, or will operate in" at 6329.01,-830.67 h45
  text "ALTIUM DESIGNER VERSION:" at 12848.5,-923.5 h45
  text "an implementation. TI and/or its licensors do not warrant that the design is production worthy. You should" at 6329.01,-943.33 h45
  text "completely validate and test your design implementation to confirm the system functionality for your application." at 6374,-1056 h45
  text ".print_Scale" at 11393.5,-1056.83 h70
  text ".Application_BuildNumber" at 12899,-1056.83 h70
  text "1" at 739.84,-1263.5 h70
  text "2" at 3235.5,-1263.5 h70
  text "3" at 5724.84,-1263.5 h70
  text "4" at 8231.51,-1263.5 h70
  text "5" at 10730.5,-1263.5 h70
  text "6" at 13235.5,-1263.5 h70
M10 Fab Notes:
  drawing of 189 lines, arcs and shapes, not listed
  text "ALL VIAS ARE NON TENTED" at 11310,6647 h60
  text "THIS IS NOT AN IMPEDENCE CONTROLLED  BOARD" at 11302,6524 h60
  text "DESIGN INFORMATION" at 12382.02,6356.17 h60
  text "MIN. TRACK WIDTH:" at 11737.46,6224.05 h60
  text "8" at 12833.7,6224.05 h60
  text "MIL" at 12988.46,6224.05 h60
  text "MIN. CLEARANCE:" at 11737.46,6099.92 h60
  text "0.2" at 12773.7,6099.93 h60
  text "mm" at 12988.46,6099.92 h60
  text "MIN. VIA PAD SIZE:" at 11737.46,5975.8 h60
  text "24" at 12803.71,5975.8 h60
  text "MIL" at 12988.46,5975.8 h60
  text "0.05mm (2MIL)" at 12432.46,5845.9 h60
  text "MINIMUM ANNULAR RING" at 11408.23,5837.67 h60
  text "EXTERNAL" at 13140.46,5837.67 h60
  text "PER" at 11608.23,5727.55 h60
  text "IPC-D-275 CLASS 2 LEVEL C" at 11828.23,5727.54 h60
  text "MIL, HOLES" at 13316.46,5627.07 h60
  text "+/-" at 12924,5618.48 h60
  text "+/-" at 13778,5618.48 h60
  text "REGISTRATION TOLERANCES:" at 11408.23,5617.42 h60
  text "METAL" at 12608,5617.42 h60
  text "5" at 13184.2,5617.42 h60
  text "3" at 14017.2,5617.42 h60
  text "MIL" at 14133.46,5617.42 h60
  text "HOLE SIZE TOLERANCE (UNLESS OTHERWISE SPECIFIED):" at 11408.23,5519.1 h60
  text "+/-" at 13778,5516.23 h60
  text "3" at 14017.2,5515.17 h60
  text "MIL" at 14133.46,5515.17 h60
  text "MATERIAL:" at 11333.46,5377.52 h60
  text "FR-4 High Tg" at 12319.9,5249 h60
  text "X" at 12175.46,5241.01 h60
  text "FR-408" at 11754.46,5236.49 h60
  text "OTHER" at 13242.46,5236.49 h60
  text "62 MIL (1.6mm) +/-10%" at 12074.56,5093.46 h60
  text "X" at 11954.46,5091.01 h60
  text "THICKNESS:" at 11408.23,5085.24 h60
  text "OTHER" at 13359.46,5085.24 h60
  text "TOLERANCE:" at 11408.23,4946.92 h60
  text "X" at 12256.46,4946.92 h60
  text "ANSI IPC-6012 TYPE 3 CLASS 2" at 12434.48,4946.92 h60
  text "OTHER +/-" at 12434.46,4802.73 h60
  text "BOW & TWIST:" at 11408.23,4657.54 h60
  text "X" at 12256.46,4657.54 h60
  text "ANSI IPC-6012 TYPE 3 CLASS 2" at 12434.48,4657.54 h60
  text "OTHER +/-" at 12434.46,4510.85 h60
  text "DRILLING:" at 11333.46,4380.23 h60
  text "NC_DRILL FILES" at 13094.46,4275.04 h60
  text "REFERENCE:" at 11408.23,4271.1 h60
  text "X" at 12065.46,4271.01 h60
  text "AS SHOWN" at 12243.46,4271.1 h60
  text "X" at 12966.46,4271.1 h60
  text "OTHER" at 13392.46,4128.85 h60
  text "PTH COPPER THICKNESS:" at 11407.91,4125.32 h60
  text "X" at 12547.14,4125.32 h60
  text "20-30 um" at 12675.14,4125.32 h60
  text "BOARD FINISH:" at 11333.46,3977.73 h60
  text "SILKSCREEN:" at 11488.68,3867.6 h60
  text "X" at 12446.46,3867.6 h60
  text "TOP" at 12563.46,3867.6 h60
  text "X" at 12956.46,3867.6 h60
  text "BOTTOM" at 13074.46,3867.6 h60
  text "SILKSCREEN COLOR:" at 11488.68,3712.41 h60
  text "X" at 12445.46,3712.41 h60
  text "WHITE" at 12563.46,3712.41 h60
  text "OTHER" at 13074.46,3712.41 h60
  text "X" at 12576.46,3568.96 h60
  text "GREEN" at 12694.46,3568.96 h60
  text "OTHER" at 13312.46,3568.96 h60
  text "SOLDER RESIST COLOR:" at 11488.68,3562.1 h60
  text "X" at 12576.46,3414.71 h60
  text "MATTE" at 12694.46,3414.71 h60
  text "SEMI-GLOSS" at 13312,3414.07 h60
  text "IMMERSION GOLD (ENIG)" at 12394.46,3241.94 h60
  text "ENEPIG" at 13732,3234.72 h60
  text "SURFACE FINISH:" at 11333.46,3233.72 h60
  text "X" at 12216.46,3233.72 h60
  text "IMM. TIN/SILVER OR EQUIV" at 11663,3096.4 h60
  text "OTHER" at 13094.46,3092.47 h60
  text "ARRAY/PANEL:" at 11333.46,2937.09 h60
  text "CUT AND TRIM PER M1 BOARD OUTLINE" at 12394.46,2928.87 h60
  text "N.C. ROUTE" at 12394.46,2792.9 h60
  text "X" at 13082.46,2792.9 h60
  text "V. SCORE" at 13260.46,2792.9 h60
  text "CERTIFICATION:" at 11333.46,2663.77 h60
  text "MATERIALS AND WORKMANSHIP FOR ALL PCBS" at 12058.46,2663.77 h60
  text "TO MEET OR EXCEED THE REQUIREMENTS OF:" at 12058.46,2569.71 h60
  text "X" at 11695.97,2441.08 h60
  text "ANSI IPC-A-600F CLASS ->" at 11823.96,2441.08 h60
  text "X" at 13471.97,2441.08 h60
  text "2" at 13581.96,2441.08 h60
  text "1" at 13266.96,2439.58 h60
  text "3" at 13935.96,2439.58 h60
  text "X" at 12507.97,2293.39 h60
  text "RoHS" at 12635.96,2293.39 h60
  text "OTHER" at 13280.36,2293.39 h60
  text "PER ORDER" at 13677.42,2293.39 h60
  text "ALL BOARDS MUST MEET OR EXCEED UL94-V0 REQUIREMENTS." at 11361,2139.57 h60
  text "PCB MUST BEAR THE UL94V-0 UL REGISTERED MATERIAL ID NUMBER" at 11361,2023.5 h60
  text "ADDITIONAL REQUIREMENTS:" at 11333.46,1854.08 h60
  text "MICROSECTION:" at 11408.23,1746.95 h60
  text "YES" at 12313.96,1746.95 h60
  text "REQUIRED" at 13175.46,1602.62 h60
  text "BARE BOARD ELEC. TEST:" at 11408.23,1599.76 h60
  text "NONE" at 12713.96,1599.76 h60
  text "X" at 13057.46,1599.76 h60
  text "PER ORDER" at 13767.46,1599.76 h60
  text "XX MIL VIAS REQUIRE NON-CONDUCTIVE FILL AND PLANARIZE" at 11576.38,1394.82 h59
  text "XX MIL VIAS REQUIRE CONDUCTIVE FILL AND PLANARIZE" at 11584.38,1290.84 h60
  text "OUTER XX MIL TRACES REQUIRE 50 OHM SINGLE-ENDED IMPEDANCE" at 11583.39,1127.46 h58
  text "LAYER 2 & 3 (INNER LAYERS) XX MIL WIDE, XX MIL SPACE / TRACES REQUIRE 100 OHM DIFFERENTIAL IMPEDANCE" at 11575.39,891.74 h60
M11 Gerber Information:
  lines w10: -292,-930.17 6308,-930.17 ; -292,-726.83 6310,-726.83 ; -292,-523.5 -292,-1133.5 3713,-1133.5 6310,-1133.5 6310,-523.5 -291.5,-523.5 -291.5,-1133.5 1284,-1133.5 ; 2173,-1133.5 2173,-523.5 ; 3440,-726.83 3440,-523.5 ; 4280,-726.83 4280,-523.5 ; 4902,-1140 4902,-937.17
  text "ALL ARTWORK VIEWED FROM TOP SIDE" at -228.5,-655.67 h60
  text "BOARD #:" at 2248,-655.67 h60
  text "TIDA-020018" at 2793.5,-655.67 h60
  text "REV:" at 3638,-655.67 h60
  text ".PCB_Rev" at 3929.5,-655.67 h60
  text "SVN REV:" at 4476,-655.67 h60
  text ".VersionControl_RevNumber" at 4982,-655.67 h60
  text "LAYER NAME =" at -228.5,-858.49 h60
  text "TID #:" at 2248,-859 h60
  text "020018" at 2793.5,-859 h60
  text "PLOT NAME =" at -228.5,-1064.34 h60
  text ".plot_File_Name" at 577,-1064.34 h60
  text "GENERATED    :" at 2250,-1064.34 h60
  text ".Print_Date" at 3119.5,-1064.34 h60
  text ".Print_Time" at 3848.5,-1064.34 h60
  text "TEXAS INSTRUMENTS" at 5113,-1064.34 h60
M12 Stackup:
  drawing of 191 lines, arcs and shapes, not listed
  text "Layer" at 3497.84,1960 h60
  text "Name" at 3907.76,1960 h60
  text "Material" at 4837.5,1960 h60
  text "Thickness" at 5697.27,1960 h60
  text "Constant" at 6347.1,1960 h60
  text "Board Layer Stack" at 6916.96,1960 h60
  text "1" at 3497.84,1840 h60
  text "Top Overlay" at 3907.76,1840 h60
  text "2" at 3497.84,1720 h60
  text "Top Solder" at 3907.76,1720 h60
  text "Solder Resist" at 4837.5,1720 h60
  text "0.40mil" at 5697.27,1720 h60
  text "3.5" at 6347.1,1720 h60
  text "3" at 3497.84,1600 h60
  text "Top Layer" at 3907.76,1600 h60
  text "Copper" at 4837.5,1600 h60
  text "1.40mil" at 5697.27,1600 h60
  text "4" at 3497.84,1480 h60
  text "Dielectric1" at 3907.76,1480 h60
  text "FR-4" at 4837.5,1480 h60
  text "59.20mil" at 5697.27,1480 h60
  text "4.8" at 6347.1,1480 h60
  text "5" at 3497.84,1360 h60
  text "Bottom Layer" at 3907.76,1360 h60
  text "Copper" at 4837.5,1360 h60
  text "1.40mil" at 5697.27,1360 h60
  text "6" at 3497.84,1240 h60
  text "Bottom Solder" at 3907.76,1240 h60
  text "Solder Resist" at 4837.5,1240 h60
  text "0.40mil" at 5697.27,1240 h60
  text "3.5" at 6347.1,1240 h60
  text "7" at 3497.84,1120 h60
  text "Bottom Overlay" at 3907.76,1120 h60
M13 Component Bodies Top:
  text ".Layer_Name" at 577,-858.49 h60
M14 Component Bodies Bottom:
  text ".Layer_Name" at 577,-858.49 h60
M15 Courtyards Top:
  text ".Layer_Name" at 577,-858.49 h60
M16 Courtyards Bottom:
  text ".Layer_Name" at 577,-858.49 h60
Drill Drawing:
  circle w10: c3513.62,482.35 r27.59
  lines w10: 3486.03,261.62 3541.21,261.62 3513.62,206.44 3486.03,261.62 ; 3486.03,330.6 3541.21,330.6 3541.21,385.78 3486.03,385.78 3486.03,330.6 ; 3486.03,592.72 3499.83,592.72 3499.83,578.92 3527.42,578.92 3527.42,592.72 3541.21,592.72 3541.21,620.31 3527.42,620.31 3527.42,634.11 3499.83,634.11 3499.83,620.31 3486.03,620.31 3486.03,592.72
  lines w12: 3436,169.19 6135.44,169.19 ; 3436,665.84 6135.44,665.84 ; 3773.58,45.03 3773.58,790 ; 4105.26,45.03 4105.26,790 ; 4741.31,45.03 4741.31,790 ; 5000.17,45.03 5000.17,790 ; 5375.09,45.03 5375.09,790 ; 3436,45.03 6135.44,45.03 6135.44,790 3436,790 3436,45.03
  text "Drill table:" at 3495,864 h60
  text "Drill tolarence:" at 6415,774 h60
  text "Symbol" at 3510.5,703.09 h72
  text "Quantity" at 3810.82,703.09 h72
  text "Finished Hole Size" at 4142.51,703.09 h72
  text "Plated" at 4778.56,703.09 h72
  text "Hole Type" at 5037.42,703.09 h72
  text "Drill Layer Pair" at 5412.34,703.09 h72
  text "For 15 mil vias+0/-15mil" at 6429,664 h60
  text "36" at 3810.82,578.92 h60
  text "15.00mil (0.381mm)" at 4142.51,578.92 h60
  text "PTH" at 4778.56,578.92 h60
  text "Round" at 5037.42,578.92 h60
  text "Top Layer - Bottom Layer" at 5412.34,578.92 h60
  text "For  PTH +/-3mil" at 6422,538 h60
  text "26" at 3810.82,454.76 h60
  text "28.00mil (0.711mm)" at 4142.51,454.76 h60
  text "PTH" at 4778.56,454.76 h60
  text "Round" at 5037.42,454.76 h60
  text "Top Layer - Bottom Layer" at 5412.34,454.76 h60
  text "For  NPTH +/-2mil" at 6432,434 h60
  text "10" at 3810.82,330.6 h60
  text "40.00mil (1.016mm)" at 4142.51,330.6 h60
  text "PTH" at 4778.56,330.6 h60
  text "Round" at 5037.42,330.6 h60
  text "Top Layer - Bottom Layer" at 5412.34,330.6 h60
  text "2" at 3810.82,206.44 h60
  text "50.00mil (1.270mm)" at 4142.51,206.44 h60
  text "PTH" at 4778.56,206.44 h60
  text "Round" at 5037.42,206.44 h60
  text "Top Layer - Bottom Layer" at 5412.34,206.44 h60
  text "74 Total" at 3810.82,82.27 h60
  text ".Layer_Name" at 577,-858.49 h60
M17 Embedded Cavity:
  text ".Layer_Name" at 577,-858.49 h60
M18 Embedded Assembly:
  text ".Layer_Name" at 577,-858.49 h60
M19 Embedded Keepout:
  text ".Layer_Name" at 577,-858.49 h60

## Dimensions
0,-400 to 1000,-400 on M2 Board Dimensions
0,0 to 0,1500 on M2 Board Dimensions
0,0 to 1945,0 on M2 Board Dimensions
